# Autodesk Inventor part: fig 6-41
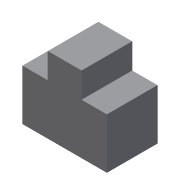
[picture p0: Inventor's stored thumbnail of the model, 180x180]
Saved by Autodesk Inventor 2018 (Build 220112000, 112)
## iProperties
Created: 2005-12
Part Number: fig 6-41
Document SubType Name: Modeling
Designer: CADCIM
Density: 1 g/cm^3
Material: Generic
Appearance: Default
Author: CADCIM
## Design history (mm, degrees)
sketch "Sketch1"
  geometry: L1 (10, 15)-(25, 15); L2 (25, 15)-(25, -15); L3 (25, -15)-(-25, -15); L4 (-25, -15)-(-25, 15); L5 (-25, 15)-(-10, 15); L6 (10, 15)-(10, 30); L7 (10, 30)-(-10, 30); L8 (-10, 30)-(-10, 15)
  constraints: 16 end point, 3 parallel, 3 perpendicular, 2 equal length, 1 collinear, 1 horizontal
  dimensions: "d0" = 50 distance of L2.end L3.end; "d2" = 30 distance of L1.end L2.end; "d3" = 15 distance of L1.start L1.end; "d11" = 15 distance of L7.end L5.end
extrude "Extrusion1" new body sketch "Sketch1" stored distance "d7" = 30; taper "d8" = 0 deg
body "Solid1"
